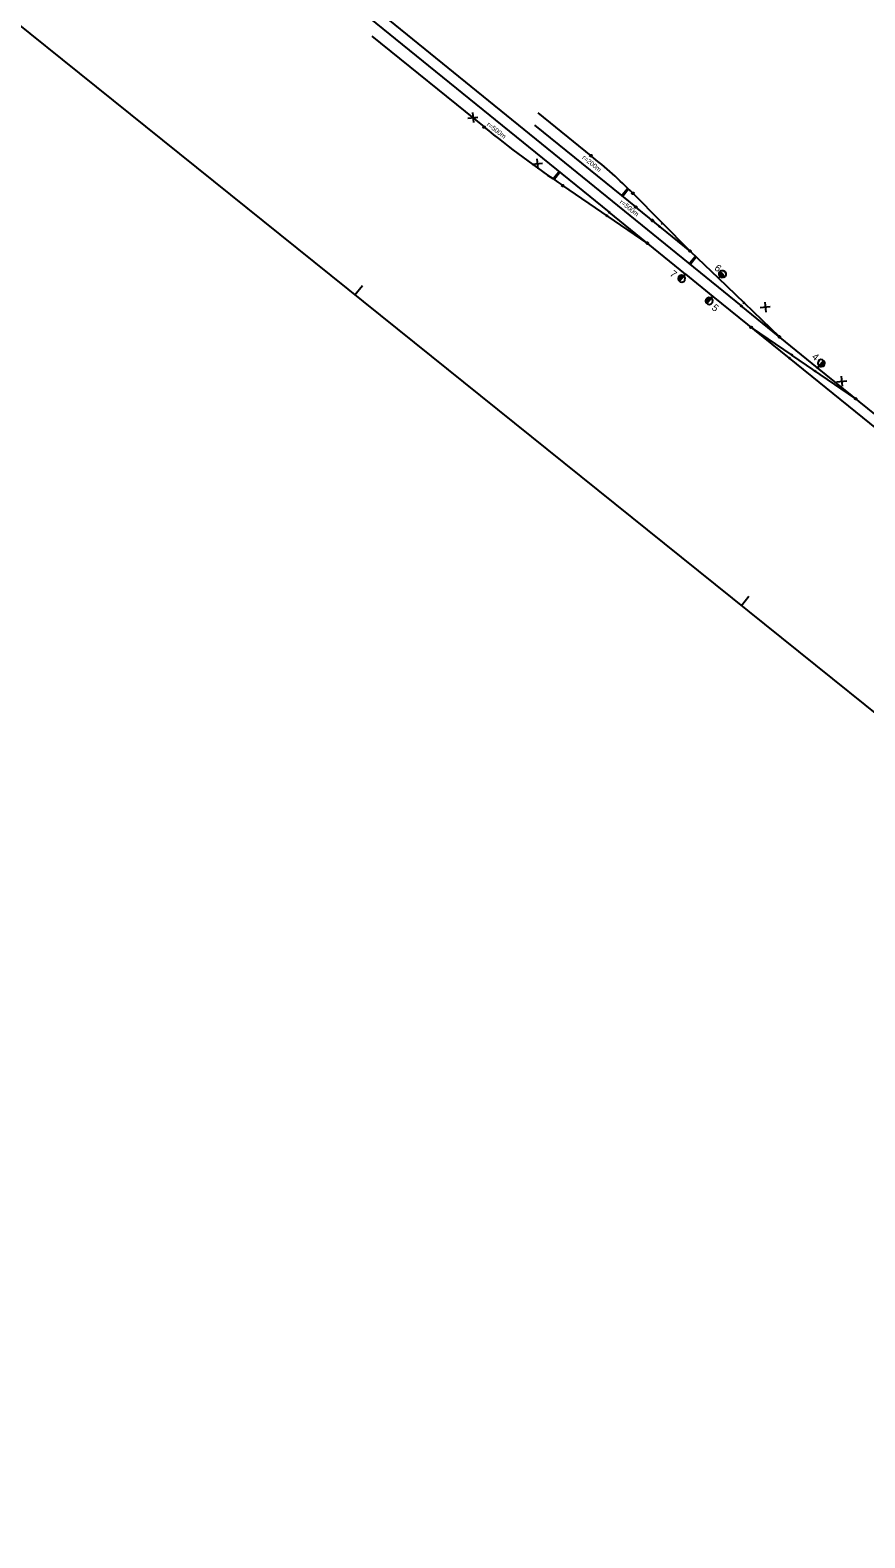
# Model space of a CAD drawing. Extents: x -491586 to -489736, y -1309039 to -1307479.
# Drawn here: x -490742 to -490388, y -1309026 to -1308388 of the extents above; entities that cross this region are included whole.
import ezdxf

# ---------------------------------------------------------------- set-up
doc = ezdxf.new("R2010")
doc.units = 0
for name, color, linetype in [('Level 1', 7, 'Continuous'), ('Level 10', 7, 'Continuous'), ('Level 11', 7, 'Continuous'), ('Level 61', 7, 'Continuous')]:
    doc.layers.add(name, color=color, linetype=linetype)

msp = doc.modelspace()

# ---------------------------------------------------------------- linework, layer by layer
at = {"layer": 'Level 1'}
for p, q in [((-490636.28, -1308345.77), (-490440.43, -1308504.75)), ((-490639.18, -1308349.35), (-490496.37, -1308465.13)), ((-490596.86, -1308390.51), (-490549.34, -1308429.03)), ((-490549.34, -1308429.03), (-490549.34, -1308429.03)), ((-490527.97, -1308428.27), (-490484.51, -1308463.47)), ((-490526.5, -1308423.02), (-490504.13, -1308441.2)), ((-490504.13, -1308441.2), (-490504.13, -1308441.2)), ((-490480.22, -1308478.22), (-490515.99, -1308453.85)), ((-490515.99, -1308453.85), (-490515.99, -1308453.85)), ((-490462.09, -1308481.56), (-490486.34, -1308457.11)), ((-490486.34, -1308457.11), (-490486.34, -1308457.11)), ((-490497.68, -1308466.93), (-490497.12, -1308466.1)), ((-490497.4, -1308466.51), (-490497.4, -1308466.51)), ((-490496.69, -1308465.52), (-490496.06, -1308464.74)), ((-490464.06, -1308491.32), (-490496.37, -1308465.13)), ((-490496.37, -1308465.13), (-490496.37, -1308465.13)), ((-490485.09, -1308462.9), (-490485.09, -1308462.9)), ((-490462.09, -1308481.56), (-490484.51, -1308463.47)), ((-490478.11, -1308468.65), (-490478.11, -1308468.65)), ((-490475.33, -1308471.51), (-490474.71, -1308470.74)), ((-490475.02, -1308471.13), (-490475.02, -1308471.13)), ((-490474.14, -1308470.11), (-490473.43, -1308469.41)), ((-490474.14, -1308470.11), (-490473.43, -1308469.41)), ((-490473.79, -1308469.76), (-490473.79, -1308469.76)), ((-490473.79, -1308469.76), (-490473.79, -1308469.76)), ((-490480.22, -1308478.22), (-490480.22, -1308478.22)), ((-490462.09, -1308481.56), (-490462.09, -1308481.56)), ((-490462.09, -1308481.56), (-490450.1, -1308493.07)), ((-490464.06, -1308491.32), (-490452.41, -1308500.77)), ((-490424.28, -1308517.86), (-490450.1, -1308493.07)), ((-490452.41, -1308500.77), (-490420.1, -1308526.96)), ((-490440.74, -1308505.14), (-490440.11, -1308504.36)), ((-490408.13, -1308530.96), (-490440.43, -1308504.75)), ((-490440.43, -1308504.75), (-490440.43, -1308504.75)), ((-490439.63, -1308503.81), (-490438.93, -1308503.09)), ((-490439.28, -1308503.45), (-490439.28, -1308503.45)), ((-490436.26, -1308513.87), (-490436.26, -1308513.87)), ((-490436.26, -1308513.87), (-490419.07, -1308525.58)), ((-490424.28, -1308517.86), (-490424.28, -1308517.86)), ((-490419.79, -1308526.58), (-490420.42, -1308527.35)), ((-490420.1, -1308526.96), (-490240.37, -1308672.68)), ((-490420.1, -1308526.96), (-490420.1, -1308526.96)), ((-490418.79, -1308525.16), (-490419.35, -1308525.99)), ((-490391.98, -1308544.07), (-490419.07, -1308525.58)), ((-490419.07, -1308525.58), (-490419.07, -1308525.58)), ((-490408.45, -1308531.35), (-490407.82, -1308530.57)), ((-490375.84, -1308557.18), (-490408.13, -1308530.96)), ((-490408.13, -1308530.96), (-490408.13, -1308530.96)), ((-490409.44, -1308532.76), (-490408.88, -1308531.94)), ((-490409.16, -1308532.35), (-490409.16, -1308532.35)), ((-490391.98, -1308544.07), (-490391.98, -1308544.07))]:
    msp.add_line(p, q, dxfattribs=at)
for points in [[(-490549.09, -1308428.72), (-490548.95, -1308429.09), (-490549.2, -1308429.4), (-490549.6, -1308429.34), (-490549.74, -1308428.97), (-490549.49, -1308428.66), (-490549.09, -1308428.72)], [(-490504.35, -1308441.53), (-490504.52, -1308441.17), (-490504.3, -1308440.84), (-490503.9, -1308440.87), (-490503.73, -1308441.23), (-490503.95, -1308441.56), (-490504.35, -1308441.53)], [(-490516.22, -1308454.18), (-490516.39, -1308453.82), (-490516.17, -1308453.49), (-490515.77, -1308453.52), (-490515.59, -1308453.88), (-490515.82, -1308454.21), (-490516.22, -1308454.18)], [(-490486.56, -1308457.44), (-490486.73, -1308457.08), (-490486.51, -1308456.75), (-490486.11, -1308456.78), (-490485.94, -1308457.14), (-490486.16, -1308457.47), (-490486.56, -1308457.44)], [(-490485.4, -1308462.65), (-490485.03, -1308462.51), (-490484.72, -1308462.76), (-490484.78, -1308463.16), (-490485.15, -1308463.3), (-490485.46, -1308463.05), (-490485.4, -1308462.65)], [(-490478.42, -1308468.4), (-490478.05, -1308468.25), (-490477.74, -1308468.5), (-490477.8, -1308468.9), (-490478.18, -1308469.04), (-490478.49, -1308468.79), (-490478.42, -1308468.4)], [(-490480.53, -1308477.97), (-490480.16, -1308477.83), (-490479.85, -1308478.08), (-490479.91, -1308478.48), (-490480.28, -1308478.62), (-490480.59, -1308478.37), (-490480.53, -1308477.97)], [(-490462.4, -1308481.31), (-490462.03, -1308481.16), (-490461.72, -1308481.41), (-490461.78, -1308481.81), (-490462.15, -1308481.95), (-490462.46, -1308481.7), (-490462.4, -1308481.31)], [(-490435.94, -1308514.12), (-490436.32, -1308514.26), (-490436.63, -1308514.01), (-490436.57, -1308513.61), (-490436.19, -1308513.47), (-490435.88, -1308513.72), (-490435.94, -1308514.12)], [(-490424.59, -1308517.6), (-490424.22, -1308517.46), (-490423.91, -1308517.71), (-490423.97, -1308518.11), (-490424.34, -1308518.25), (-490424.65, -1308518), (-490424.59, -1308517.6)], [(-490392.29, -1308543.82), (-490391.92, -1308543.68), (-490391.61, -1308543.93), (-490391.67, -1308544.32), (-490392.05, -1308544.46), (-490392.36, -1308544.21), (-490392.29, -1308543.82)]]:
    msp.add_lwpolyline(points, dxfattribs=at)
for centre, radius, start, end in [((-490234.45, -1308040.65), 500, 230.96523, 235.73035), ((-490628.34, -1308597.95), 200, 44.76398, 51.60643)]:
    msp.add_arc(centre, radius, start, end, dxfattribs=at)
at = {"layer": 'Level 10'}
for p, q in [((-490517.69, -1308448.16), (-490519.9, -1308450.87)), ((-490517.33, -1308448.45), (-490519.54, -1308451.16)), ((-490488.63, -1308455.18), (-490490.84, -1308457.89)), ((-490488.27, -1308455.47), (-490490.48, -1308458.18)), ((-490459.96, -1308483.94), (-490462.17, -1308486.65)), ((-490459.6, -1308484.23), (-490461.81, -1308486.94))]:
    msp.add_line(p, q, dxfattribs=at)
at = {"layer": 'Level 11'}
for p, q in [((-490554.28, -1308422.9), (-490553.85, -1308427.15)), ((-490556.19, -1308425.24), (-490551.94, -1308424.81)), ((-490528.9, -1308444.8), (-490524.65, -1308444.37)), ((-490526.99, -1308442.46), (-490526.56, -1308446.71)), ((-490464.06, -1308491.32), (-490466.59, -1308494.36)), ((-490464.06, -1308491.32), (-490464.06, -1308491.32)), ((-490450.1, -1308493.07), (-490449.41, -1308492.34)), ((-490449.84, -1308491.63), (-490449.81, -1308490.92)), ((-490449.41, -1308492.34), (-490449.84, -1308491.63)), ((-490449.81, -1308490.92), (-490449.45, -1308490.22)), ((-490449.17, -1308490.8), (-490449.64, -1308491.29)), ((-490449.64, -1308491.29), (-490449.56, -1308491.64)), ((-490449.56, -1308491.64), (-490448.83, -1308490.88)), ((-490449.45, -1308490.22), (-490448.82, -1308489.86)), ((-490448.55, -1308491.02), (-490449.42, -1308491.92)), ((-490449.42, -1308491.92), (-490449.41, -1308492.34)), ((-490449.41, -1308492.34), (-490448.31, -1308491.2)), ((-490449.41, -1308492.34), (-490448.31, -1308491.2)), ((-490448.67, -1308492.74), (-490449.41, -1308492.34)), ((-490449.41, -1308492.34), (-490448.68, -1308492.74)), ((-490448.98, -1308492.34), (-490449.41, -1308492.34)), ((-490448.12, -1308491.43), (-490448.98, -1308492.34)), ((-490448.82, -1308489.86), (-490448.07, -1308489.8)), ((-490448.7, -1308492.47), (-490447.97, -1308491.71)), ((-490448.34, -1308492.53), (-490448.7, -1308492.47)), ((-490447.94, -1308492.71), (-490448.67, -1308492.74)), ((-490447.87, -1308492.04), (-490448.34, -1308492.53)), ((-490448.07, -1308489.8), (-490447.33, -1308490.18)), ((-490447.29, -1308492.3), (-490447.94, -1308492.71)), ((-490447.33, -1308490.18), (-490446.9, -1308490.9)), ((-490446.91, -1308491.66), (-490447.29, -1308492.3)), ((-490446.9, -1308490.9), (-490446.91, -1308491.66)), ((-490452.41, -1308500.77), (-490454.94, -1308503.8)), ((-490452.41, -1308500.77), (-490452.41, -1308500.77)), ((-490432.4, -1308505.52), (-490428.15, -1308505.09)), ((-490430.49, -1308503.18), (-490430.06, -1308507.43)), ((-490408.13, -1308530.96), (-490405.65, -1308527.89)), ((-490408.13, -1308530.96), (-490408.13, -1308530.96)), ((-490400.05, -1308536.93), (-490395.8, -1308536.49)), ((-490398.14, -1308534.58), (-490397.71, -1308538.84))]:
    msp.add_line(p, q, dxfattribs=at)
for points in [[(-490466.9, -1308494.1), (-490466.29, -1308494.61), (-490465.53, -1308494.74), (-490464.81, -1308494.48), (-490464.29, -1308493.86), (-490464.17, -1308493.11), (-490464.43, -1308492.39), (-490465.04, -1308491.87), (-490465.8, -1308491.75), (-490466.52, -1308492.01), (-490467.03, -1308492.62), (-490467.16, -1308493.38), (-490466.9, -1308494.1), (-490466.93, -1308493.75), (-490466.55, -1308494.07), (-490466.36, -1308493.84), (-490467.01, -1308493.29), (-490466.93, -1308492.97), (-490466.16, -1308493.61), (-490465.97, -1308493.38), (-490466.85, -1308492.64), (-490466.66, -1308492.41), (-490465.78, -1308493.15), (-490465.59, -1308492.92), (-490466.47, -1308492.18), (-490466.16, -1308492.05), (-490465.39, -1308492.69), (-490465.2, -1308492.46), (-490465.86, -1308491.91), (-490465.36, -1308491.94), (-490465.01, -1308492.22)], [(-490455.25, -1308503.55), (-490454.63, -1308504.06), (-490453.88, -1308504.18), (-490453.15, -1308503.93), (-490452.64, -1308503.31), (-490452.52, -1308502.55), (-490452.78, -1308501.83), (-490453.39, -1308501.32), (-490454.15, -1308501.19), (-490454.87, -1308501.45), (-490455.38, -1308502.07), (-490455.51, -1308502.82), (-490455.25, -1308503.55), (-490455.28, -1308503.19), (-490454.9, -1308503.51), (-490454.7, -1308503.28), (-490455.36, -1308502.74), (-490455.28, -1308502.41), (-490454.51, -1308503.05), (-490454.32, -1308502.82), (-490455.2, -1308502.09), (-490455.01, -1308501.86), (-490454.13, -1308502.59), (-490453.93, -1308502.36), (-490454.82, -1308501.63), (-490454.51, -1308501.49), (-490453.74, -1308502.13), (-490453.55, -1308501.9), (-490454.2, -1308501.36), (-490453.7, -1308501.38), (-490453.36, -1308501.67)], [(-490405.34, -1308528.14), (-490405.97, -1308527.64), (-490406.72, -1308527.52), (-490407.44, -1308527.79), (-490407.94, -1308528.42), (-490408.06, -1308529.18), (-490407.76, -1308529.92), (-490407.17, -1308530.39), (-490406.4, -1308530.51), (-490405.68, -1308530.24), (-490405.18, -1308529.61), (-490405.07, -1308528.86), (-490405.34, -1308528.14), (-490405.3, -1308528.49), (-490405.69, -1308528.18), (-490405.88, -1308528.41), (-490405.22, -1308528.94), (-490405.25, -1308529.3), (-490406.07, -1308528.64), (-490406.26, -1308528.88), (-490405.36, -1308529.6), (-490405.55, -1308529.83), (-490406.45, -1308529.11), (-490406.64, -1308529.34), (-490405.74, -1308530.07), (-490406.04, -1308530.2), (-490406.82, -1308529.58), (-490407.01, -1308529.81), (-490406.35, -1308530.34), (-490406.85, -1308530.33), (-490407.2, -1308530.04)]]:
    msp.add_lwpolyline(points, dxfattribs=at)
msp.add_arc((-490449.35, -1308492.29), 1.5, 344.39202, 107.93688, dxfattribs=at)
at = {"layer": 'Level 61'}
for p, q in [((-489949.39, -1309026.46), (-491094.92, -1308105.24)), ((-490603.98, -1308500.05), (-490600.84, -1308496.15)), ((-490440.33, -1308631.65), (-490437.2, -1308627.75))]:
    msp.add_line(p, q, dxfattribs=at)

# ---------------------------------------------------------------- texts
at = {"layer": 'Level 10'}
for s, rotation, p in [('r=500m', 322.16445, (-490548.41, -1308428.34)), ('r=200m', 321.09445, (-490508.01, -1308442.3)), ('r=500m', 321.09445, (-490492.09, -1308461.15))]:
    msp.add_text(s, height=2, rotation=rotation, dxfattribs=at).set_placement(p)
at = {"layer": 'Level 11'}
for s, p in [('7', (-490470.96, -1308491.71)), ('6', (-490452.08, -1308489.22)), ('5', (-490453.21, -1308506.06)), ('4', (-490410.79, -1308526.82))]:
    msp.add_text(s, height=3, rotation=321.19445, dxfattribs=at).set_placement(p)

doc.saveas('drawing.dxf')
